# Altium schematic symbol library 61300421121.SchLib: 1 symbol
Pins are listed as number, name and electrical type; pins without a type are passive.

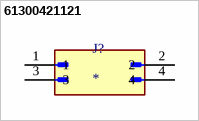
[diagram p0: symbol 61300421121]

## 61300421121
designator J?
Connector Header Through Hole 4 position 0.100 (2.54mm); MF: WÃ¼rth Elektronik; MP: 61300421121
footprint WURTH_61300421121
pins: 1, 2, 3, 4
